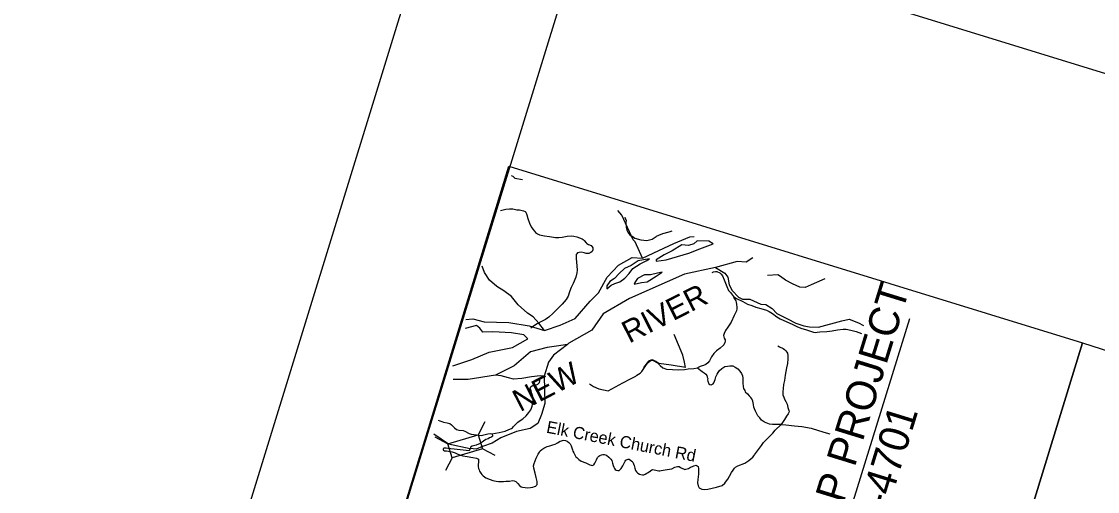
# Model space of a CAD drawing. Extents: x 1348011 to 1349268, y 1028333 to 1030014.
# Drawn here: x 1348011.3 to 1348346.3, y 1028980.8 to 1029127.1 of the extents above; entities that cross this region are included whole.
import ezdxf

# ---------------------------------------------------------------- set-up
doc = ezdxf.new("R2010")
doc.units = 0
for name, color, linetype in [('CTL Sheet Border CELL', 7, 'Continuous'), ('Prop Leader Line Light', 7, 'Continuous'), ('Prop Leader Line Medium', 7, 'Continuous'), ('Prop WCC CELL', 7, 'Continuous'), ('Scratch_Level_3', 7, 'Continuous'), ('Sheet Data Field CELL', 7, 'Continuous')]:
    doc.layers.add(name, color=color, linetype=linetype)

msp = doc.modelspace()

# ---------------------------------------------------------------- linework, layer by layer
at = {"layer": 'CTL Sheet Border CELL'}
msp.add_lwpolyline([(1348395.15, 1029993.01), (1348011.26, 1028746.43), (1348883.85, 1028477.71), (1349267.74, 1029724.29)], close=True, dxfattribs=at)
at = {"layer": 'Prop Leader Line Medium'}
for p, q in [((1348287.74, 1029034.54), (1348266.45, 1028965.92)), ((1348155.56, 1029002.41), (1348153.44, 1028998.46)), ((1348144.07, 1028995.53), (1348140.11, 1028997.65)), ((1348158.72, 1028991.95), (1348154.77, 1028994.07)), ((1348145.36, 1028991.24), (1348143.25, 1028987.29))]:
    msp.add_line(p, q, dxfattribs=at)
for points in [[(1348163.69, 1029079.16), (1348164.2, 1029078.94), (1348164.83, 1029078.32), (1348167.24, 1029077.85)], [(1348160.42, 1029068.29), (1348160.84, 1029068.34), (1348162.08, 1029068.61), (1348163.18, 1029068.8), (1348164.22, 1029068.8), (1348165.45, 1029068.46), (1348166.28, 1029068.45), (1348167.52, 1029068.17), (1348168.04, 1029067.96), (1348168.18, 1029067.87), (1348168.29, 1029067.71), (1348168.57, 1029066.91), (1348168.96, 1029065.79), (1348169.41, 1029064.35), (1348169.97, 1029063.12), (1348170.48, 1029062.38), (1348170.99, 1029061.76), (1348171.34, 1029061.43), (1348171.98, 1029060.98), (1348172.6, 1029060.69), (1348174.11, 1029060.33), (1348175.63, 1029060.13), (1348177.55, 1029059.88), (1348178.62, 1029059.87), (1348179.61, 1029059.96), (1348181.17, 1029060.25), (1348182.64, 1029060.32), (1348183.28, 1029060.23), (1348184.14, 1029060.04), (1348185.79, 1029059.47), (1348186.16, 1029059.22), (1348186.44, 1029058.92), (1348187.08, 1029058.17), (1348187.34, 1029057.97), (1348187.83, 1029057.68), (1348188.6, 1029057.35), (1348188.96, 1029056.94), (1348189.18, 1029056.58), (1348189.2, 1029056.24), (1348189.16, 1029056), (1348188.95, 1029055.48), (1348188.55, 1029055.15), (1348187.88, 1029054.87), (1348187.13, 1029054.86), (1348186.47, 1029055.04), (1348185.5, 1029055.23), (1348184.87, 1029055.22), (1348184.43, 1029055.03), (1348184.15, 1029054.79), (1348184, 1029054.59), (1348183.96, 1029054.35), (1348183.95, 1029053.27), (1348184.18, 1029051.03), (1348184.25, 1029049.72), (1348184.22, 1029048.85), (1348183.82, 1029047.48), (1348183.04, 1029045.57), (1348182.41, 1029044.27), (1348181.94, 1029042.96), (1348181.53, 1029041.56), (1348180.83, 1029040.53), (1348179.56, 1029039.07), (1348178.13, 1029037.62), (1348176.84, 1029036.33), (1348175.46, 1029035.02), (1348174.4, 1029034.32), (1348172.99, 1029033.57), (1348171.8, 1029033), (1348170.97, 1029032.48), (1348170.3, 1029031.95), (1348169.86, 1029031.63)], [(1348204.62, 1029053.45), (1348202.39, 1029058.47), (1348201.69, 1029059.06), (1348198.19, 1029066.8), (1348196.98, 1029068.24)], [(1348199.11, 1029066.17), (1348199.15, 1029066.14), (1348199.28, 1029065.89), (1348199.5, 1029065.15), (1348199.42, 1029064.52), (1348199.59, 1029063.04), (1348199.82, 1029061.94), (1348200.06, 1029061.53), (1348200.23, 1029061.18), (1348200.56, 1029060.78), (1348200.77, 1029060.42), (1348201.41, 1029060.21), (1348202.19, 1029059.62), (1348204.14, 1029059.11), (1348205.94, 1029058.94), (1348207.62, 1029059.33), (1348208.83, 1029060.1)], [(1348149.62, 1029034.27), (1348151.77, 1029034.5), (1348155.34, 1029033.6), (1348162.96, 1029033.39), (1348169.29, 1029032.36), (1348174.14, 1029030.89), (1348178.96, 1029032.58), (1348183.61, 1029034.67), (1348188.37, 1029040.04), (1348190.89, 1029042.6), (1348193.6, 1029047.54), (1348197.15, 1029051.18), (1348201.36, 1029053.58), (1348204.62, 1029053.45), (1348209.71, 1029055.77), (1348214.41, 1029058.02), (1348219.37, 1029060.01), (1348220.71, 1029060.17)], [(1348213.78, 1029061.77), (1348212.83, 1029061.5), (1348210.85, 1029060.94), (1348209.58, 1029060.51), (1348208.83, 1029060.1)], [(1348208.9, 1029052.46), (1348212, 1029052.92), (1348219.03, 1029054.91), (1348222.48, 1029056.36), (1348226.68, 1029057.86), (1348225.25, 1029058.7), (1348221.69, 1029058.79), (1348220.56, 1029057.91), (1348218.94, 1029057.36), (1348216.9, 1029057.51), (1348213.85, 1029055.65), (1348211.34, 1029054.44), (1348208.84, 1029052.88), (1348208.9, 1029052.46)], [(1348238.96, 1029053.56), (1348236.89, 1029052.12), (1348234.07, 1029052.39), (1348227.35, 1029050.48), (1348217.71, 1029048.47), (1348200.62, 1029040.89), (1348192.34, 1029036.06), (1348188.82, 1029031.02), (1348181.71, 1029026.94), (1348181.31, 1029026.51)], [(1348193.5, 1029043.85), (1348194.82, 1029044.96), (1348196.03, 1029045.52), (1348197.52, 1029046.05), (1348199.13, 1029047.13), (1348200.45, 1029048.64), (1348201.62, 1029050.2), (1348203.89, 1029051.6), (1348205.81, 1029052.58), (1348206.79, 1029053.16), (1348204.96, 1029052.84), (1348203.32, 1029052.58), (1348201.1, 1029051.17), (1348199, 1029050.18), (1348197.33, 1029048.66), (1348195.93, 1029047.11), (1348194.49, 1029046.16), (1348193.49, 1029044.78), (1348193.5, 1029043.85)], [(1348174.14, 1029030.89), (1348172.37, 1029033.14), (1348170.55, 1029035.1), (1348168.77, 1029036.27), (1348165.96, 1029038.93), (1348163.8, 1029041.51), (1348161.41, 1029043.25), (1348159.26, 1029044.58), (1348156.99, 1029046.57), (1348155.47, 1029048.94), (1348154.74, 1029050.96)], [(1348227.35, 1029050.48), (1348230.22, 1029048.72), (1348231.16, 1029047.5), (1348231.61, 1029045.06), (1348232.52, 1029043.38), (1348234.47, 1029041.29), (1348235.73, 1029040.67), (1348238.1, 1029040.65), (1348241.48, 1029039.13), (1348243.08, 1029038.94), (1348245, 1029037.78), (1348246.47, 1029036.17), (1348249.78, 1029034.55), (1348252.37, 1029033.16), (1348254.82, 1029032.37), (1348256.67, 1029032.02), (1348259.4, 1029031.96), (1348266.72, 1029033.95), (1348268.94, 1029034.39), (1348271.85, 1029033.32), (1348273.44, 1029032.47)], [(1348202, 1029045.34), (1348204.36, 1029045.84), (1348206.09, 1029046.02), (1348208.93, 1029047.76), (1348210.76, 1029049.01), (1348209.29, 1029048.76), (1348207.11, 1029048.25), (1348205.2, 1029048.25), (1348203.09, 1029047.03), (1348202.22, 1029045.85), (1348202, 1029045.34)], [(1348226.27, 1029048.9), (1348226.71, 1029049.1), (1348227.39, 1029049.25), (1348227.8, 1029049.24), (1348228.72, 1029048.86), (1348229.16, 1029048.43), (1348229.49, 1029047.9), (1348230.01, 1029046.69), (1348230.87, 1029044.58), (1348231.43, 1029043.36), (1348232, 1029042.68), (1348232.94, 1029041.45)], [(1348257.19, 1029045.06), (1348255.32, 1029044.29), (1348253.65, 1029044.33), (1348251.34, 1029045.42), (1348249.11, 1029046.57), (1348247.59, 1029047.74), (1348246.75, 1029048.22), (1348243.56, 1029048.06)], [(1348261.38, 1029047.02), (1348258.77, 1029045.83), (1348257.19, 1029045.06)], [(1348232.94, 1029041.45), (1348233.11, 1029041.07), (1348233.64, 1029040.14), (1348233.83, 1029039.71), (1348233.94, 1029039.01), (1348233.99, 1029038.12), (1348233.99, 1029037.62), (1348233.85, 1029037.04), (1348233.13, 1029035.6), (1348232.2, 1029033.49), (1348231.18, 1029031.9), (1348230.43, 1029030.85), (1348230.05, 1029029.93), (1348229.9, 1029029.36), (1348229.93, 1029028.93), (1348230.07, 1029028.47), (1348230.34, 1029028.01), (1348230.39, 1029027.78), (1348230.36, 1029027.54), (1348230.3, 1029027.11), (1348229.92, 1029026.44), (1348228.77, 1029025.35), (1348227.68, 1029024.54), (1348226.8, 1029023.78), (1348226.09, 1029022.72), (1348225.46, 1029021.42), (1348224.99, 1029020.85), (1348224.35, 1029020.33), (1348223.57, 1029020), (1348223.2, 1029019.86), (1348222.61, 1029019.7), (1348222.12, 1029019.48), (1348221.72, 1029019.24)], [(1348232.94, 1029041.45), (1348233.9, 1029040.81), (1348235.85, 1029039.89), (1348237.35, 1029039.11), (1348238.62, 1029038.66), (1348239.96, 1029038.18), (1348241.45, 1029037.74), (1348243.23, 1029037.21), (1348244.02, 1029036.83), (1348245.1, 1029036.15), (1348246.5, 1029035.19), (1348247.46, 1029034.55), (1348249.55, 1029033.58), (1348251.19, 1029032.84), (1348252.73, 1029032.18), (1348253.97, 1029031.65), (1348255.67, 1029031.1), (1348257.89, 1029030.38), (1348258.49, 1029030.31), (1348259.01, 1029030.35), (1348259.87, 1029030.45), (1348261.99, 1029030.55), (1348263.65, 1029030.81), (1348265.36, 1029031.05), (1348267.07, 1029031.32), (1348268.05, 1029031.26), (1348269.51, 1029030.99), (1348271.14, 1029030.63), (1348272.82, 1029029.99)], [(1348145.58, 1029019.85), (1348151.43, 1029021.85), (1348156.84, 1029024.15), (1348164.17, 1029025.6), (1348168.91, 1029028.27), (1348167.63, 1029029.53), (1348163.88, 1029030.14), (1348158.05, 1029030.5), (1348154.88, 1029030.41), (1348154.02, 1029031.57), (1348152.89, 1029032.49), (1348149.39, 1029031.48)], [(1348181.31, 1029026.51), (1348177.84, 1029025.98), (1348174.94, 1029025.63), (1348169.77, 1029024.26), (1348164.65, 1029019.93), (1348158.87, 1029016.98)], [(1348181.31, 1029026.51), (1348176.95, 1029023.22), (1348175.39, 1029021.08), (1348173.99, 1029016.7)], [(1348218.06, 1029019.39), (1348217.71, 1029021.01), (1348217.22, 1029023.2), (1348214.51, 1029029.68)], [(1348246.8, 1029026.1), (1348247.24, 1029025.79), (1348248.4, 1029025.24), (1348248.85, 1029024.97), (1348249.31, 1029024.58), (1348249.59, 1029024.15), (1348249.76, 1029023.8), (1348249.89, 1029023.14), (1348249.92, 1029022.09), (1348249.74, 1029020.64), (1348249.45, 1029019.24), (1348249.02, 1029016.98), (1348248.83, 1029015.32), (1348248.56, 1029014.11), (1348248.42, 1029012.85), (1348248.3, 1029011.8), (1348248.37, 1029010.86), (1348248.65, 1029010.12), (1348248.84, 1029009.56), (1348249.28, 1029008.77), (1348249.64, 1029007.95), (1348249.92, 1029006.92), (1348250.21, 1029006.01), (1348250.29, 1029005.61), (1348250.02, 1029005), (1348249.51, 1029004.26), (1348248.83, 1029003.15), (1348247.81, 1029001.65)], [(1348188.07, 1029014.34), (1348189.33, 1029013.5), (1348190.99, 1029012.78), (1348193.96, 1029012.1), (1348198.55, 1029014.57), (1348200.85, 1029015.85), (1348202.5, 1029016.65), (1348202.9, 1029016.98), (1348203.94, 1029017.63), (1348204.39, 1029018.1), (1348205.07, 1029019.1), (1348205.82, 1029020.3), (1348206.44, 1029020.88), (1348206.88, 1029021.34), (1348207.51, 1029021.69), (1348207.75, 1029021.63), (1348209.32, 1029020.82), (1348210.11, 1029020), (1348210.94, 1029019.28), (1348212.11, 1029018.87), (1348213.96, 1029018.78), (1348215.82, 1029018.6), (1348217.66, 1029018.7), (1348218.8, 1029018.95), (1348220.57, 1029019.09), (1348221.72, 1029019.24)], [(1348218.06, 1029019.39), (1348213.55, 1029020.07), (1348209.68, 1029020.61), (1348208.77, 1029021.25), (1348207.71, 1029021.73), (1348207.17, 1029021.68), (1348206.53, 1029021.3), (1348204.96, 1029019.41)], [(1348221.72, 1029019.24), (1348222.74, 1029018.44), (1348223.17, 1029018.09), (1348223.85, 1029017.75), (1348224.38, 1029017.3), (1348224.68, 1029016.87), (1348224.8, 1029016.33), (1348224.92, 1029015.94), (1348224.89, 1029015.52), (1348224.95, 1029015.11), (1348225.04, 1029014.83), (1348225.15, 1029014.57), (1348225.33, 1029014.28), (1348225.58, 1029014.1), (1348226.04, 1029013.99), (1348226.24, 1029014.08), (1348226.58, 1029014.3), (1348226.87, 1029014.58), (1348227.29, 1029015.59), (1348227.47, 1029016.42), (1348227.87, 1029017.34), (1348228.49, 1029018.35), (1348229.34, 1029019.06), (1348230.28, 1029019.71), (1348231.12, 1029019.78), (1348231.77, 1029019.86), (1348232.73, 1029019.86), (1348233.53, 1029019.51), (1348234.32, 1029018.94), (1348234.97, 1029018.21), (1348235.48, 1029017.53), (1348235.76, 1029016.77), (1348235.82, 1029016.09), (1348235.87, 1029015.4), (1348235.85, 1029014.52), (1348236, 1029013.46), (1348236.12, 1029012.88), (1348236.45, 1029012.2), (1348236.62, 1029011.83), (1348237.28, 1029011.19), (1348237.82, 1029010.55), (1348238.4, 1029010)], [(1348158.87, 1029016.98), (1348150.37, 1029015.68), (1348145.68, 1029015.59)], [(1348173.99, 1029016.7), (1348172.75, 1029016.73), (1348170.11, 1029016.49), (1348167, 1029015.94), (1348164.46, 1029015.79), (1348162.88, 1029016.18), (1348160.59, 1029016.79), (1348158.87, 1029016.98)], [(1348173.99, 1029016.7), (1348174.2, 1029008.15), (1348173.2, 1029004.72), (1348172.03, 1029001.92), (1348169.62, 1029000.41), (1348165.44, 1028999.44)], [(1348157.71, 1028998.73), (1348160.04, 1028999.1), (1348161.9, 1028999.58), (1348163.05, 1029000.04), (1348163.79, 1029000.39), (1348164.16, 1029000.64), (1348164.47, 1029000.96), (1348165.08, 1029001.68), (1348165.85, 1029002.39), (1348166.48, 1029002.9), (1348167.36, 1029003.44), (1348168.43, 1029004.3), (1348169.27, 1029005.36), (1348169.88, 1029006.21), (1348170.09, 1029006.72), (1348170.28, 1029007.33), (1348170.49, 1029008.47), (1348170.59, 1029009.44), (1348170.59, 1029009.94), (1348170.51, 1029010.34), (1348170.17, 1029011.24), (1348169.93, 1029012.15), (1348169.69, 1029012.81), (1348169.7, 1029013.1), (1348169.75, 1029013.25), (1348169.82, 1029013.35), (1348169.94, 1029013.48), (1348170.35, 1029013.72), (1348170.77, 1029013.71), (1348171.33, 1029013.9), (1348172.02, 1029014.22), (1348172.29, 1029014.43), (1348172.59, 1029014.71), (1348172.66, 1029015.18), (1348172.66, 1029015.43), (1348172.59, 1029015.62), (1348172.52, 1029015.77)], [(1348247.81, 1029001.65), (1348246.27, 1029001.62), (1348245.15, 1029001.67), (1348244.13, 1029001.75), (1348243.1, 1029002.16), (1348242.58, 1029002.34), (1348241.72, 1029003.03), (1348241.12, 1029003.69), (1348240.59, 1029004.36), (1348240.26, 1029004.94), (1348239.84, 1029005.73), (1348239.52, 1029006.54), (1348239.3, 1029007.03), (1348239.19, 1029007.9), (1348239.01, 1029008.9), (1348238.66, 1029009.65), (1348238.4, 1029010)], [(1348141.02, 1029003), (1348141.47, 1029002.74), (1348142.09, 1029002.52), (1348142.62, 1029002.36), (1348143.8, 1029002.17), (1348144.64, 1029001.94), (1348145.16, 1029001.49), (1348145.59, 1029001.13), (1348146.08, 1029000.64), (1348146.75, 1029000.1), (1348147.47, 1028999.9), (1348148.75, 1028999.76), (1348149.26, 1028999.51), (1348150.62, 1028998.84), (1348151.27, 1028998.66), (1348152.91, 1028998.41), (1348154.42, 1028998.17), (1348155.2, 1028998.37), (1348156.51, 1028998.75), (1348157.19, 1028998.78), (1348157.71, 1028998.73), (1348157.85, 1028998.65), (1348157.85, 1028998.48), (1348157.91, 1028998.33), (1348157.89, 1028998.04), (1348157.67, 1028997.8), (1348157.44, 1028997.62), (1348157.03, 1028997.44), (1348156.6, 1028997.22), (1348155.84, 1028996.92), (1348155.14, 1028996.44), (1348154.69, 1028996.09), (1348154.08, 1028995.74), (1348152.81, 1028995.18), (1348151.62, 1028994.86), (1348151.03, 1028994.54), (1348150.92, 1028994.16)], [(1348195.28, 1028989.57), (1348195.49, 1028988.85), (1348195.72, 1028988.33), (1348195.94, 1028987.92), (1348196.14, 1028987.66), (1348196.46, 1028987.37), (1348196.9, 1028987.29), (1348197.4, 1028987.33), (1348197.76, 1028987.74), (1348197.98, 1028987.92), (1348198.53, 1028988.72), (1348198.94, 1028989.63), (1348199.26, 1028990.23), (1348199.48, 1028990.5), (1348199.8, 1028990.76), (1348200.14, 1028990.83), (1348200.47, 1028990.81), (1348200.84, 1028990.56), (1348201.27, 1028990.25), (1348201.58, 1028989.89), (1348201.86, 1028989.35), (1348202.03, 1028988.85), (1348202.23, 1028988.08), (1348202.48, 1028987.27), (1348202.79, 1028986.86), (1348203.2, 1028986.51), (1348203.65, 1028986.2), (1348204.15, 1028986.08), (1348204.66, 1028985.99), (1348205.04, 1028986), (1348205.42, 1028986.16), (1348206.02, 1028986.43), (1348206.44, 1028986.74), (1348207.1, 1028987.2), (1348207.57, 1028987.51), (1348207.83, 1028987.63), (1348208.24, 1028987.55), (1348208.74, 1028987.4), (1348209.2, 1028987.32), (1348209.67, 1028987.22), (1348210.07, 1028987.23), (1348210.46, 1028987.27), (1348211.01, 1028987.4), (1348212.26, 1028987.58), (1348213.71, 1028987.84), (1348214.66, 1028988.3), (1348215.49, 1028988.57), (1348216.03, 1028988.56), (1348216.44, 1028988.27), (1348216.7, 1028988.16), (1348217.08, 1028987.91), (1348217.35, 1028987.8), (1348217.8, 1028987.66), (1348218.09, 1028987.69), (1348218.52, 1028987.81), (1348218.95, 1028987.95), (1348219.6, 1028988.3), (1348220.16, 1028988.54), (1348220.65, 1028988.8), (1348221.29, 1028988.95), (1348221.65, 1028988.78), (1348221.99, 1028988.51), (1348222.08, 1028987.9), (1348222.08, 1028987.56), (1348222.04, 1028986.16), (1348221.85, 1028984.51), (1348221.79, 1028983.45), (1348221.91, 1028982.5), (1348222.25, 1028981.9), (1348222.72, 1028981.69), (1348223.15, 1028981.51), (1348223.91, 1028981.44), (1348224.93, 1028981.55), (1348226.27, 1028981.83), (1348227.66, 1028982.14), (1348229.46, 1028982.68), (1348230.23, 1028983.32), (1348230.8, 1028984.12), (1348231.16, 1028984.59), (1348231.71, 1028985.53), (1348232.33, 1028986.66), (1348232.82, 1028987.42), (1348233.26, 1028987.99), (1348233.62, 1028988.33), (1348234.34, 1028988.76), (1348236.5, 1028989.59), (1348237.77, 1028990.43), (1348238.98, 1028991.49), (1348239.35, 1028991.99), (1348239.53, 1028992.22), (1348239.78, 1028992.64), (1348240.44, 1028993.47), (1348241.66, 1028995.12), (1348242.35, 1028996), (1348243.11, 1028996.87), (1348243.61, 1028997.33), (1348244.01, 1028997.72), (1348245.21, 1028998.94), (1348245.94, 1028999.84), (1348247.81, 1029001.65)], [(1348247.81, 1029001.65), (1348249.29, 1029001.51), (1348251.95, 1029001.2), (1348254.23, 1029001.05), (1348257.15, 1029000.46), (1348259.38, 1028999.74), (1348261.78, 1028999.03), (1348262.96, 1028998.75)], [(1348139.67, 1028998.77), (1348144.22, 1028995.64), (1348150.92, 1028994.16)], [(1348147.13, 1028992.36), (1348148.72, 1028991.88), (1348149.98, 1028991.67), (1348151.75, 1028991.36), (1348152.98, 1028991.14), (1348153.35, 1028990.95), (1348153.52, 1028990.85), (1348153.59, 1028990.69), (1348153.55, 1028989.9), (1348153.47, 1028989.23), (1348153.46, 1028988.59), (1348153.59, 1028987.95), (1348153.74, 1028987.5), (1348153.87, 1028987.09), (1348154.05, 1028986.76), (1348154.27, 1028986.48), (1348154.57, 1028986.07), (1348154.99, 1028985.69), (1348155.38, 1028985.35), (1348155.83, 1028985.02), (1348157.23, 1028984.48), (1348158, 1028984.22), (1348159.02, 1028984.02), (1348159.8, 1028983.93), (1348160.66, 1028983.86), (1348161.38, 1028983.86), (1348162.09, 1028983.95), (1348163.18, 1028984.01), (1348164.13, 1028984.15), (1348164.7, 1028984.06), (1348165.22, 1028983.85), (1348165.76, 1028983.3), (1348166.32, 1028982.62), (1348166.81, 1028982.27), (1348167.26, 1028982.08), (1348168.07, 1028981.99), (1348168.9, 1028981.96), (1348169.74, 1028981.98), (1348170.44, 1028982.11), (1348171.04, 1028982.29), (1348171.42, 1028982.47), (1348171.56, 1028982.65), (1348171.79, 1028982.97), (1348171.85, 1028983.33), (1348171.82, 1028983.86), (1348171.52, 1028985.11), (1348171.2, 1028986.43), (1348170.76, 1028988.07), (1348170.72, 1028988.76), (1348170.87, 1028989.44), (1348171.16, 1028990.34), (1348171.52, 1028991.18), (1348172.13, 1028992.41), (1348172.55, 1028993.06), (1348172.81, 1028993.4), (1348173.32, 1028993.82), (1348173.89, 1028994.25), (1348174.94, 1028994.77), (1348175.74, 1028994.98), (1348176.72, 1028995.29), (1348177.43, 1028995.54), (1348178.18, 1028995.92), (1348179, 1028996.43), (1348179.37, 1028996.52), (1348179.68, 1028996.63), (1348180.11, 1028996.72), (1348180.61, 1028996.64), (1348181.16, 1028996.44), (1348181.66, 1028996.06), (1348182.14, 1028995.58), (1348182.46, 1028994.96), (1348182.67, 1028994.35), (1348182.83, 1028993.71), (1348182.93, 1028993.31), (1348183.21, 1028992.76), (1348183.57, 1028992.2), (1348183.88, 1028991.59), (1348184.21, 1028991.32), (1348184.85, 1028990.72), (1348185.49, 1028990.26), (1348186.98, 1028989.69), (1348187.85, 1028989.27), (1348188.22, 1028989.12), (1348188.64, 1028988.94), (1348188.99, 1028988.85), (1348189.45, 1028989.05), (1348189.77, 1028989.6), (1348190.08, 1028990.18), (1348190.28, 1028990.65), (1348190.66, 1028991.36), (1348191.04, 1028991.77), (1348191.36, 1028992), (1348191.82, 1028992.18), (1348192.3, 1028992.27), (1348192.73, 1028992.25), (1348193.44, 1028992.04), (1348194.18, 1028991.44), (1348194.72, 1028990.89), (1348195.12, 1028990.41), (1348195.28, 1028989.57)], [(1348165.44, 1028999.44), (1348160.55, 1028997.52), (1348157.82, 1028995.85), (1348154.82, 1028994.77), (1348152.83, 1028993.91), (1348150.92, 1028994.16)], [(1348150.92, 1028994.16), (1348150.68, 1028993.48), (1348145.96, 1028993.92), (1348144.93, 1028994.06), (1348144.03, 1028994.16), (1348143.46, 1028994.23), (1348143.03, 1028994.28), (1348142.81, 1028994.24), (1348142.64, 1028994.11), (1348142.56, 1028993.91), (1348142.59, 1028993.77), (1348142.67, 1028993.69), (1348142.99, 1028993.48), (1348143.56, 1028993.4), (1348145.33, 1028993.09), (1348146.25, 1028992.81), (1348147.13, 1028992.36)]]:
    msp.add_lwpolyline(points, dxfattribs=at)
msp.add_lwpolyline([(1348154.77, 1028994.07), (1348145.37, 1028991.22), (1348144.04, 1028995.61), (1348153.44, 1028998.46)], close=True, dxfattribs=at)
at = {"layer": 'Prop WCC CELL'}
for points in [[(1348067.18, 1028769.65), (1348163, 1029082), (1348341.6, 1029027), (1348245.78, 1028714.65)], [(1348245.78, 1028714.65), (1348341.6, 1029027), (1348407.4, 1029005.91), (1348311.58, 1028693.56)]]:
    msp.add_lwpolyline(points, close=True, dxfattribs=at)
at = {"layer": 'Scratch_Level_3'}
for p, q in [((1348067.18, 1028769.65), (1348187.56, 1029160.56)), ((1348187.56, 1029160.56), (1348831.4, 1028962.29))]:
    msp.add_line(p, q, dxfattribs=at)

# ---------------------------------------------------------------- texts
at = {"layer": 'Prop Leader Line Light'}
for s, rotation, p in [('RIVER', 26.9724, (1348200.47, 1029026.78)), ('NEW', 27.2521, (1348166.51, 1029005.41))]:
    msp.add_text(s, height=6.9, rotation=rotation, dxfattribs=at).set_placement(p)
at = {"layer": 'Prop Leader Line Medium'}
msp.add_text('Elk Creek Church Rd', height=3.7631, rotation=348.8741, dxfattribs=at).set_placement((1348174.48, 1028999.12))
at = {"layer": 'Sheet Data Field CELL'}
for s, p in [('TIP PROJECT', (1348263.96, 1028966.2)), ('B-4701', (1348278.66, 1028967.2))]:
    msp.add_text(s, height=9.344, rotation=72.8834, dxfattribs=at).set_placement(p)

doc.saveas('drawing.dxf')
